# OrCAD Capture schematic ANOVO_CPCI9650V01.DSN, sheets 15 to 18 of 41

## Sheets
15 -ICH8-M HOST (1 of 4),3*SATA: size C; title: 15--ICH8-M HOST (1 of 4),3*SATA
16 -ICH8-M PCI E(2 of 4): size C; title: 16--ICH8-M PCI E(2 of 4)
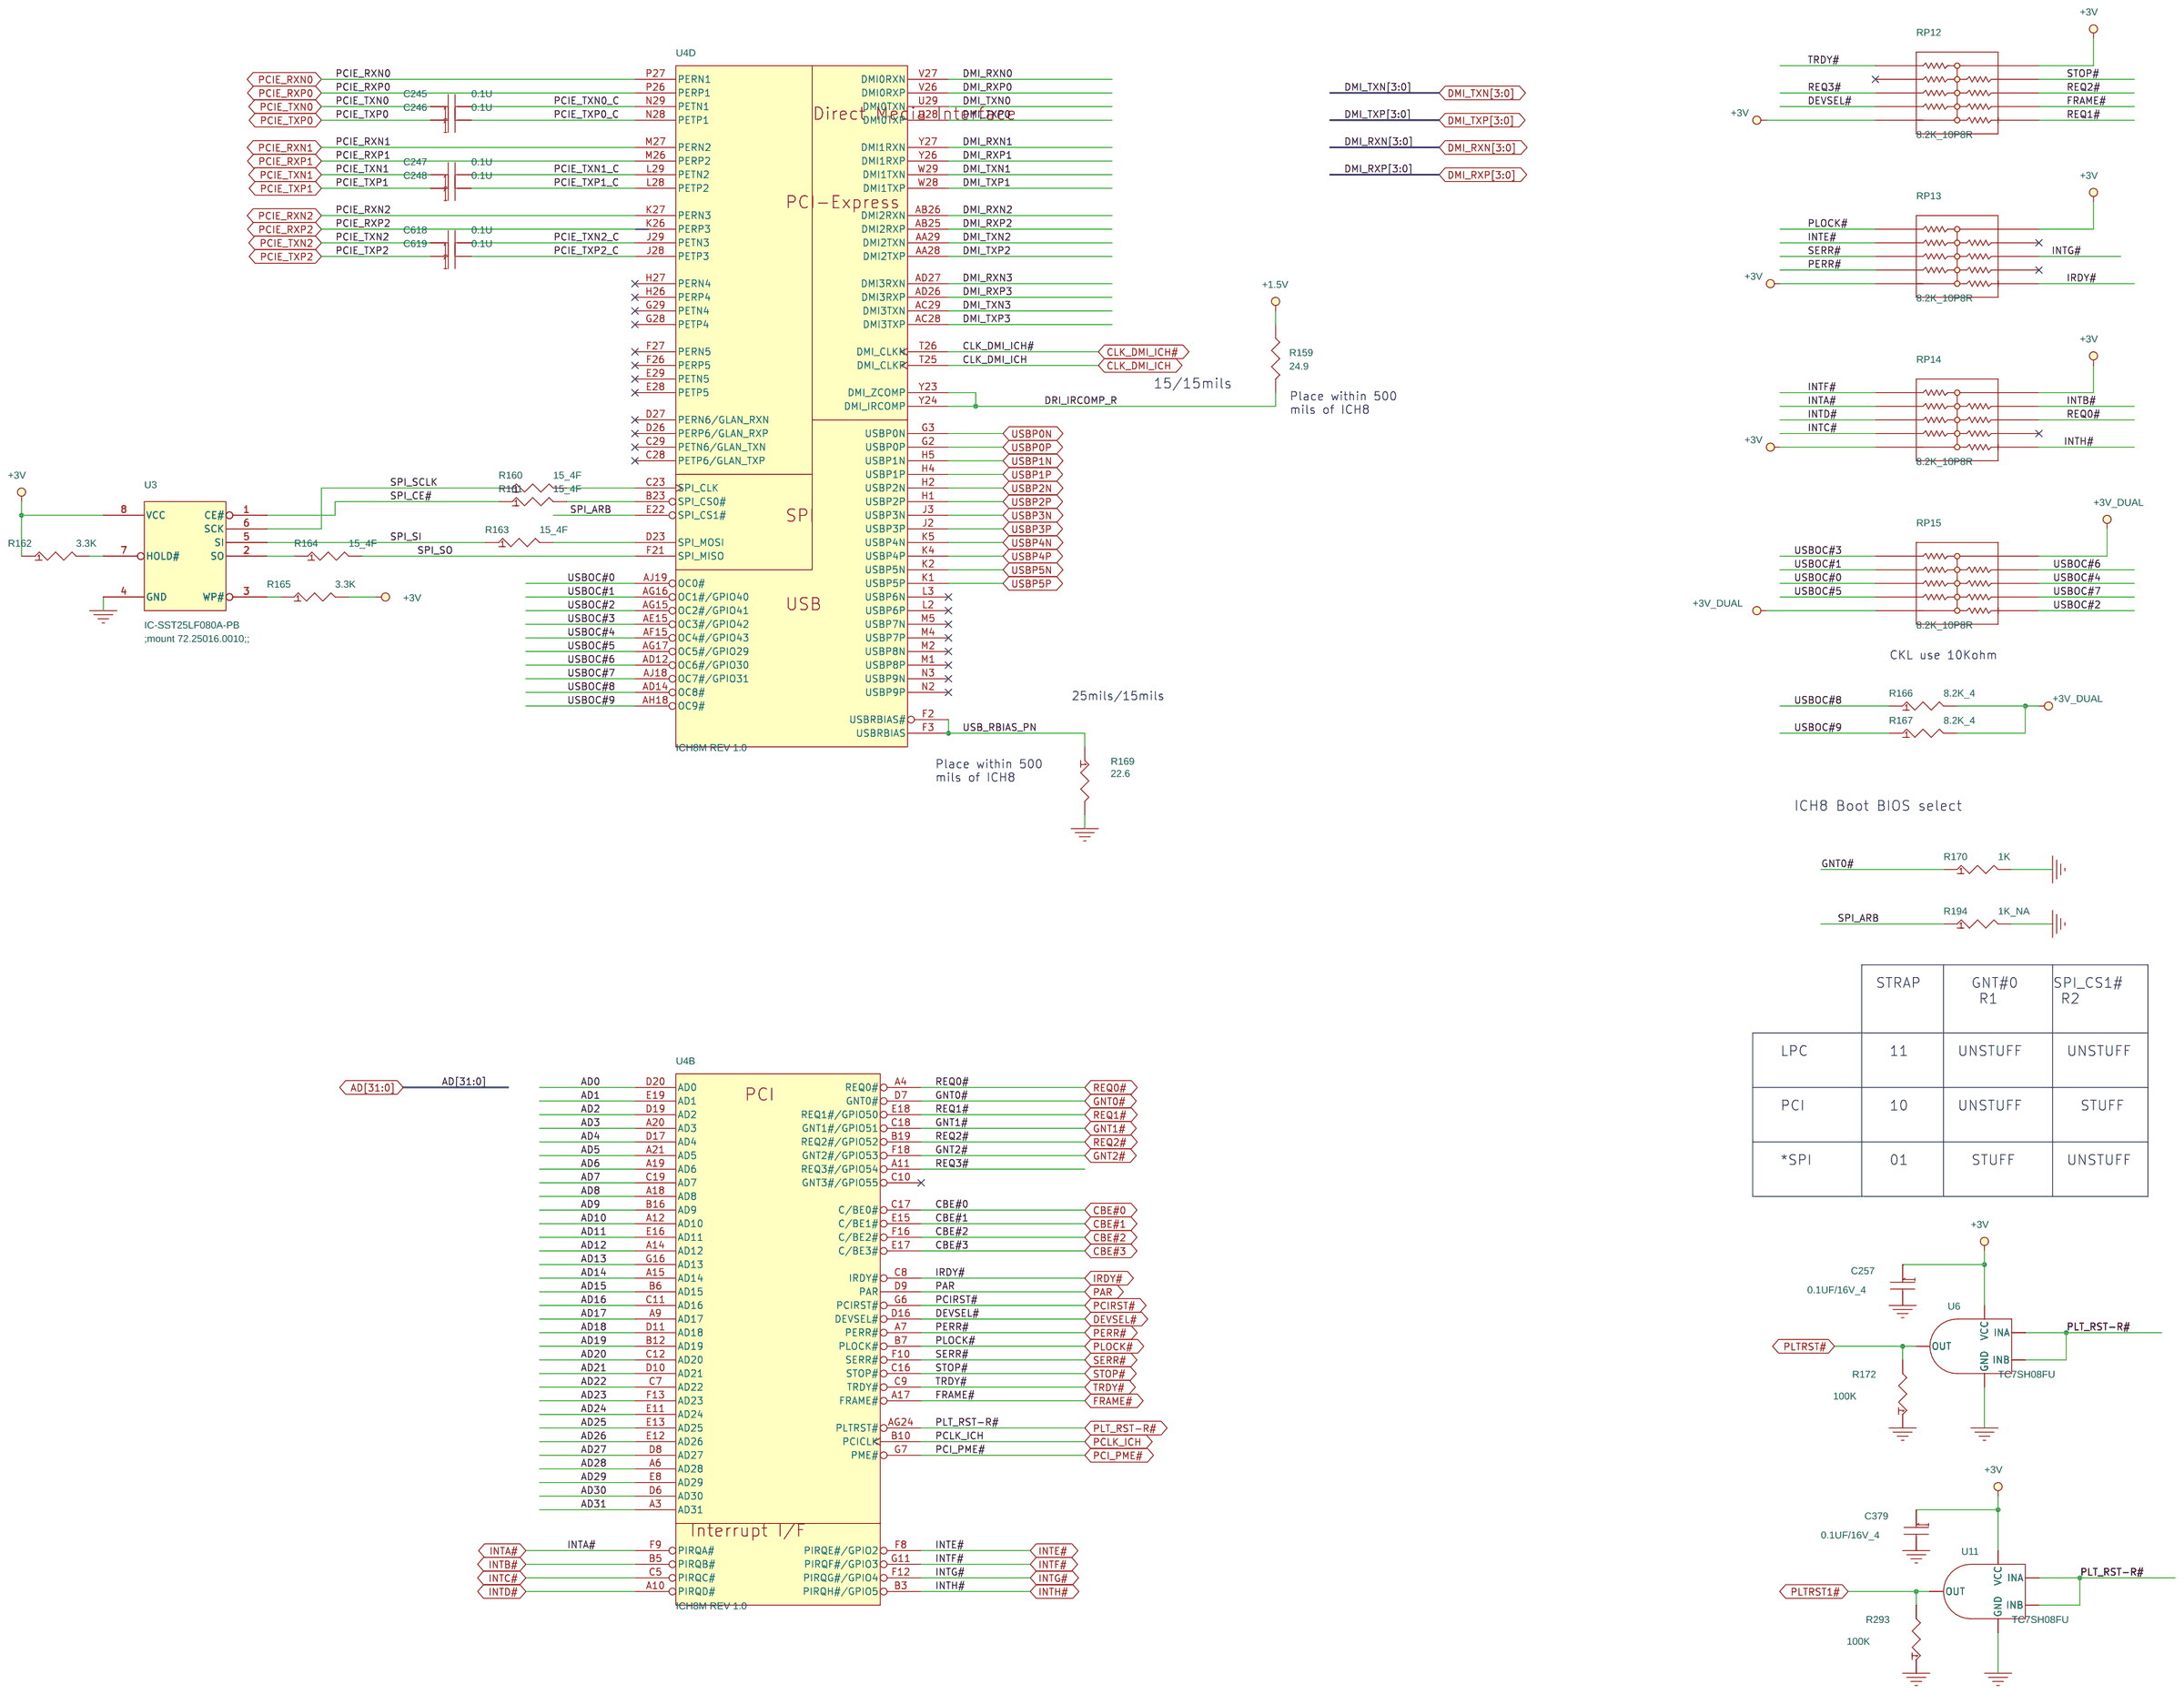
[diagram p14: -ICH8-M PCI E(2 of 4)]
17 -ICH8-M GPIO (3 of 4): size C; title: 17--ICH8-M GPIO (3 of 4)
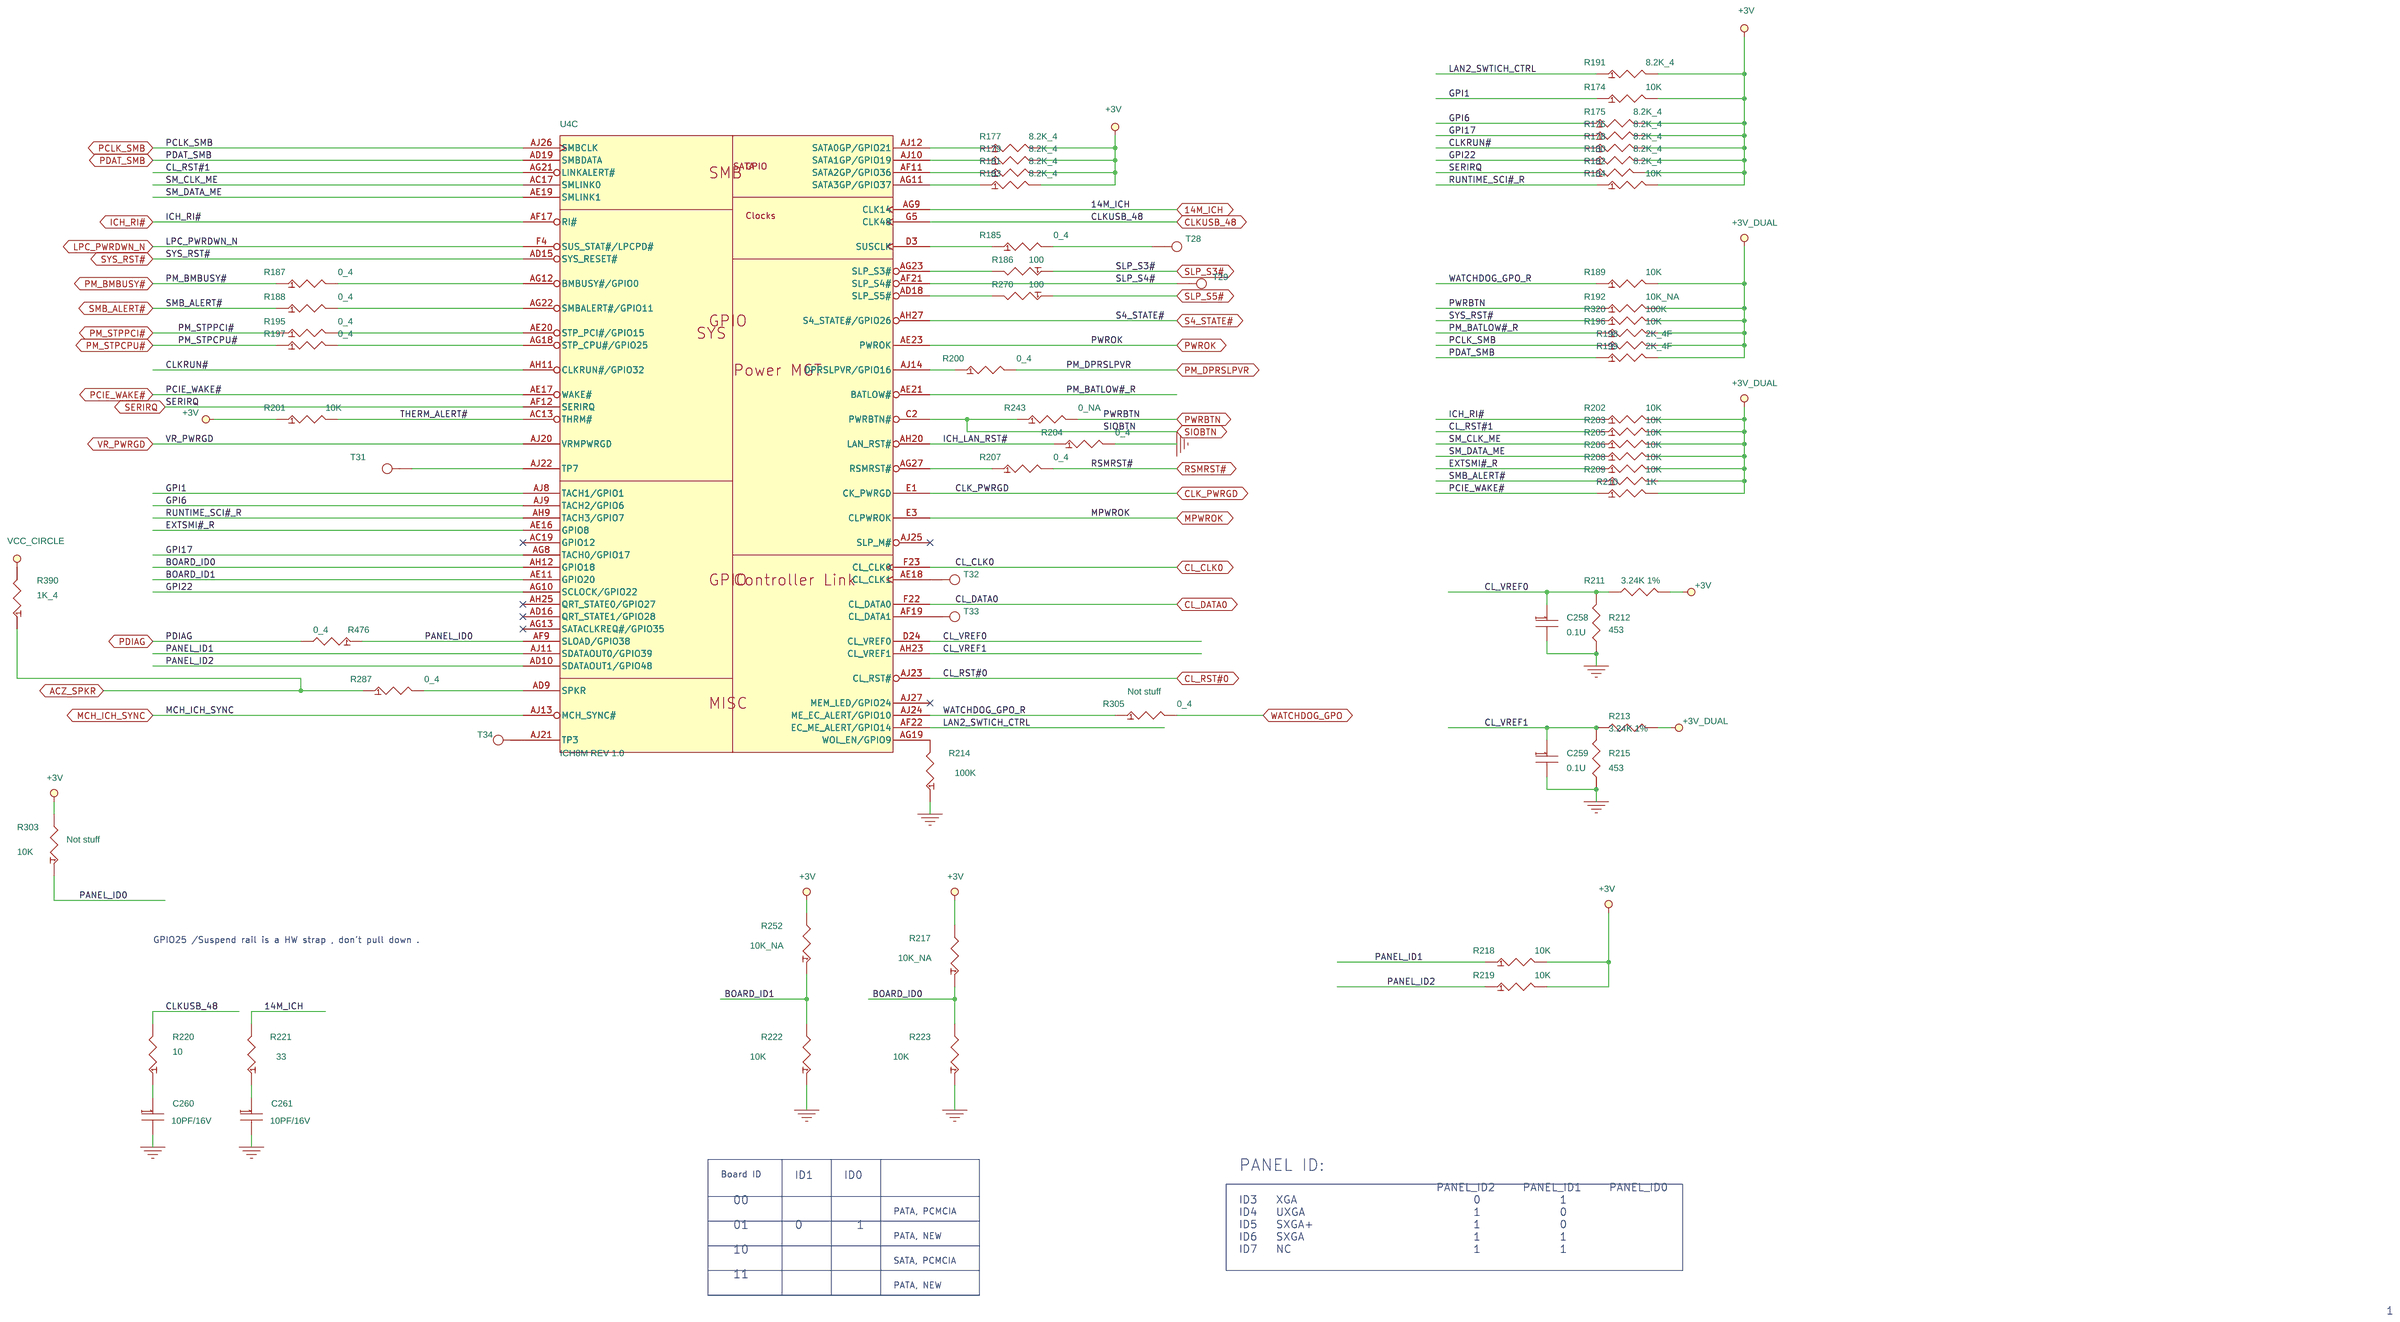
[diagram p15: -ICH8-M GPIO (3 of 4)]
18 -ICH8-M Power (4 of 4): size C; title: 18--ICH8-M Power (4 of 4)
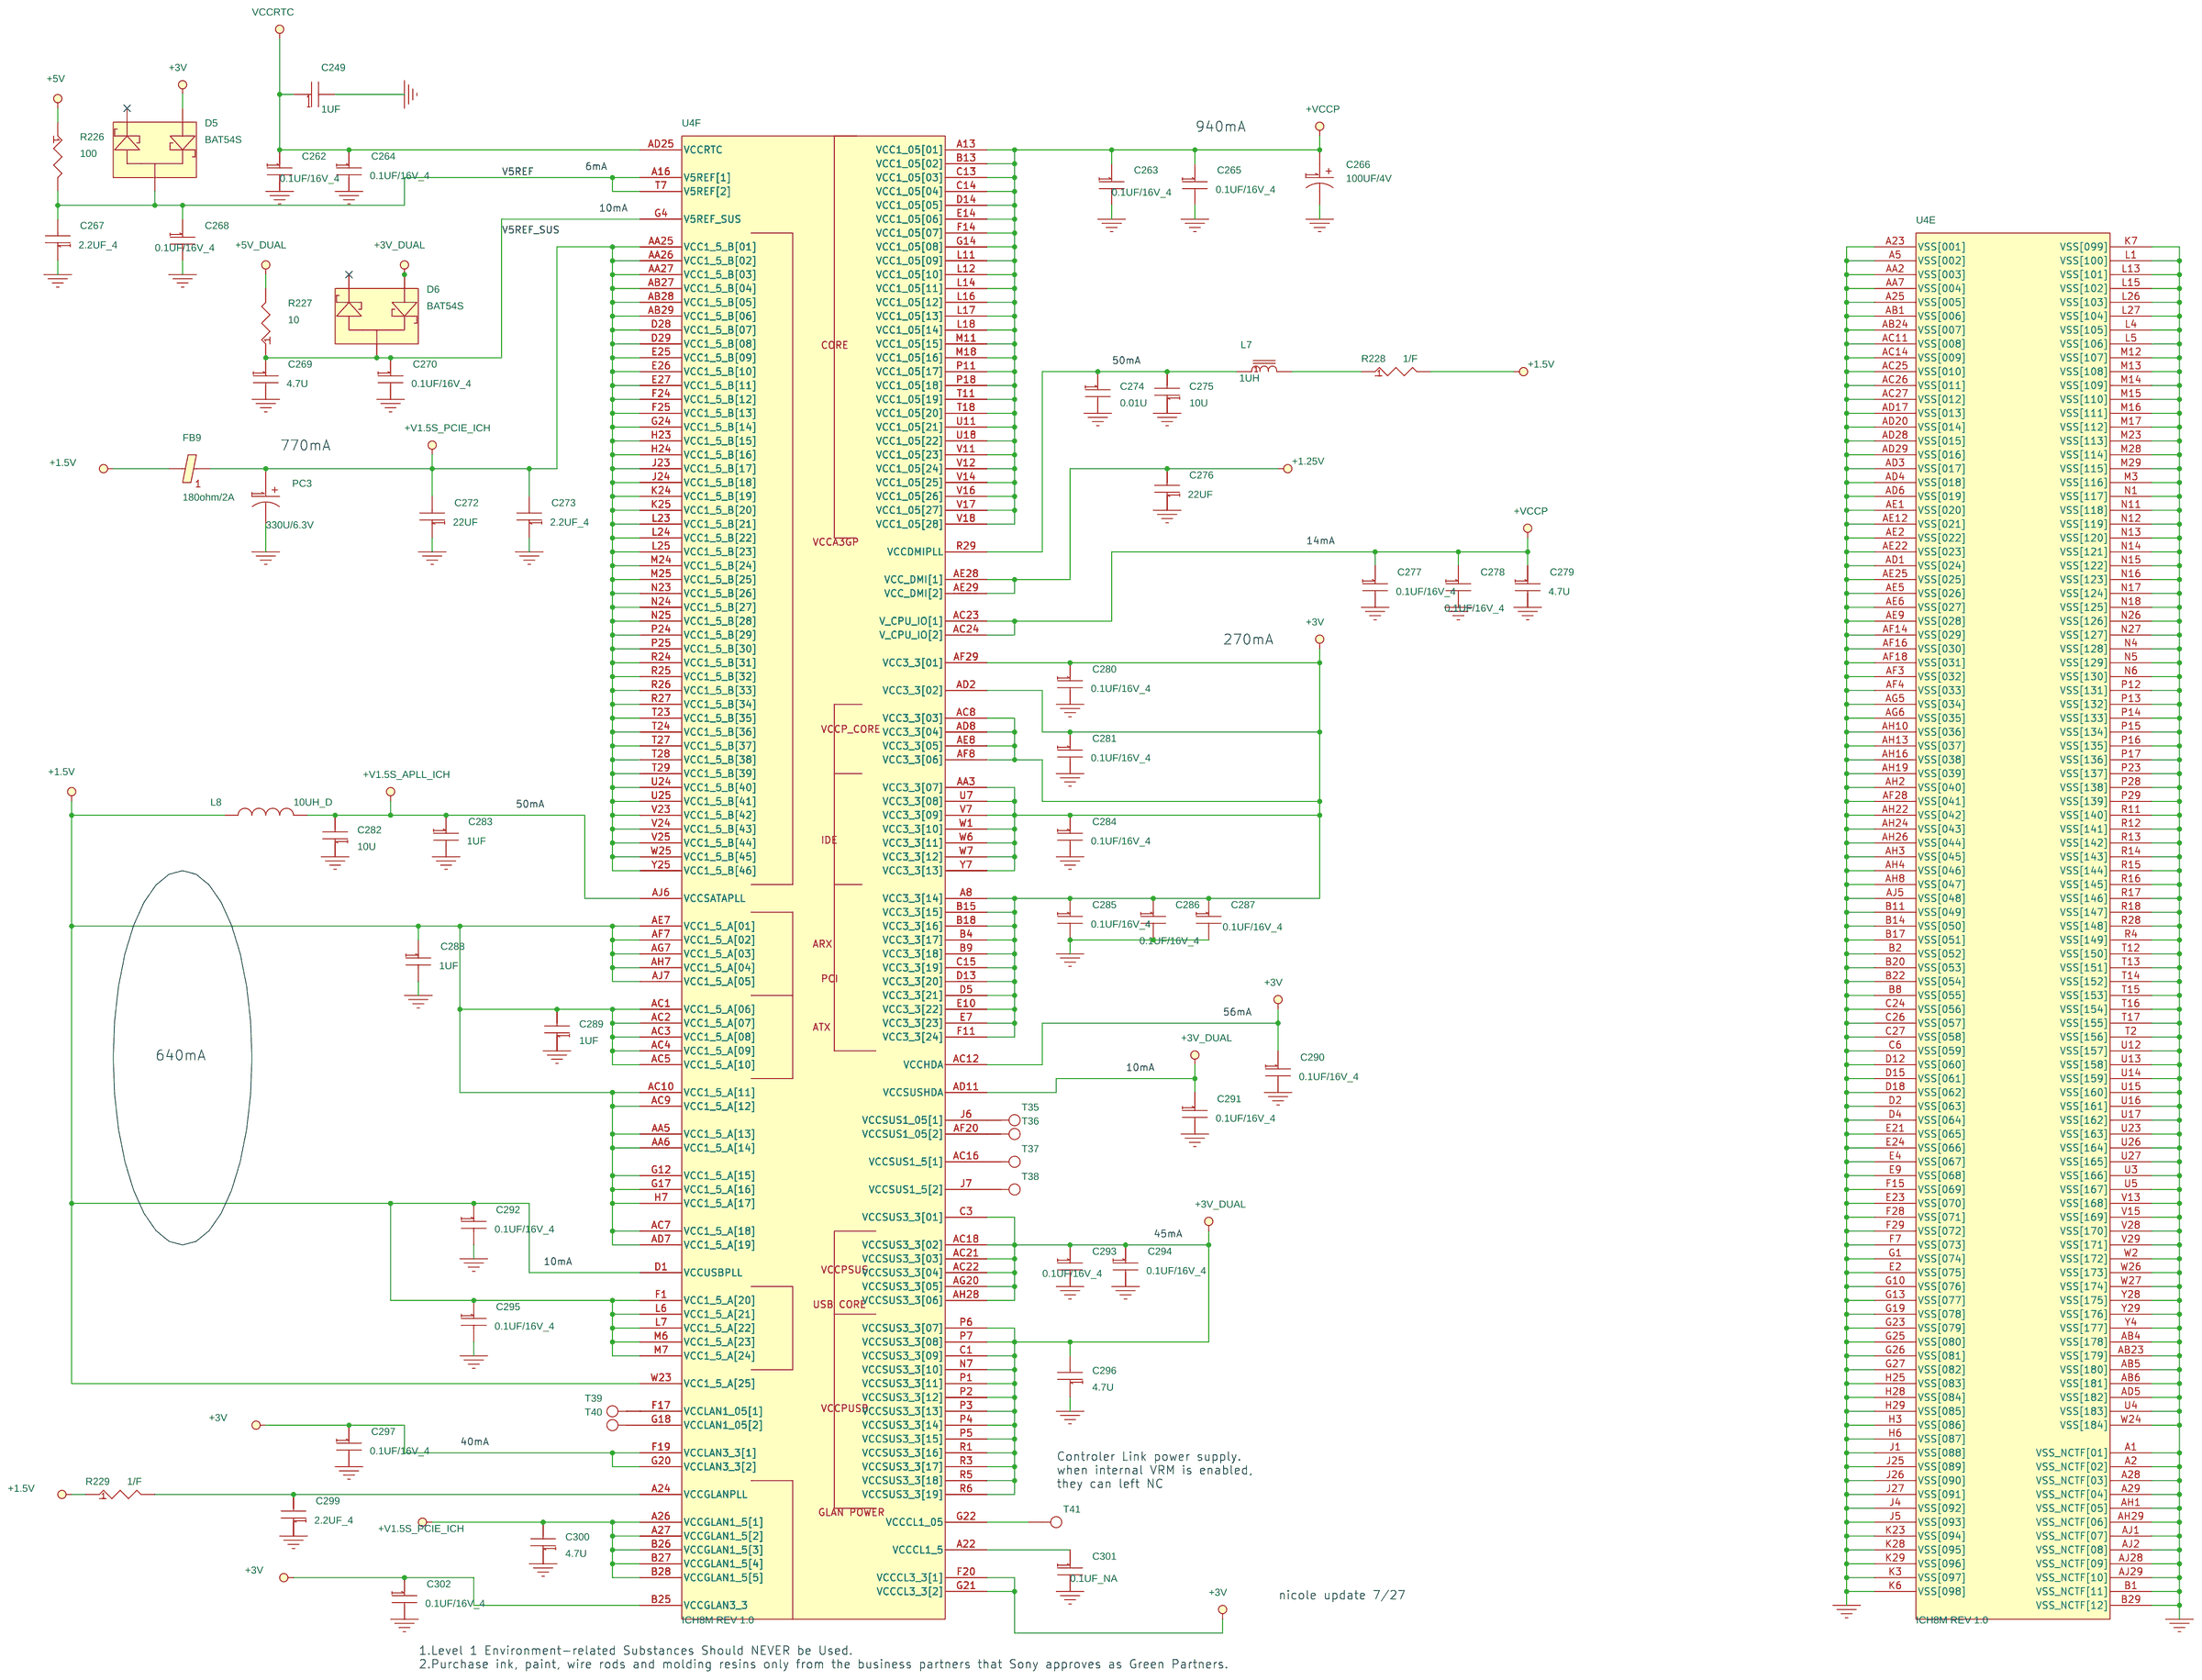
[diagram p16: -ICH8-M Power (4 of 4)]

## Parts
sheet -ICH8-M GPIO (3 of 4)
C258  0.1U  [0402D]
C259  0.1U  [0402D]
C260  10PF/16V  [0402D]
C261  10PF/16V  [0402D]
R174  10K  [0402D]
R175  8.2K_4  [0402D]
R176  8.2K_4  [0402D]
R177  8.2K_4  [0402D]
R178  8.2K_4  [0402D]
R179  8.2K_4  [0402D]
R180  8.2K_4  [0402D]
R181  8.2K_4  [0402D]
R182  8.2K_4  [0402D]
R183  8.2K_4  [0402D]
R184  10K  [0402D]
R185  0_4  [0402D]
R186  100  [0402D]
R187  0_4  [0402D]
R188  0_4  [0402D]
R189  10K  [0402D]
R191  8.2K_4  [0402D]
R192  10K_NA  [0402D]
R195  0_4  [0402D]
R196  10K  [0402D]
R197  0_4  [0402D]
R198  2K_4F  [0402D]
R199  2K_4F  [0402D]
R200  0_4  [0402D]
R201  10K  [0402D]
R202  10K  [0402D]
R203  10K  [0402D]
R204  0_4  [0402D]
R205  10K  [0402D]
R206  10K  [0402D]
R207  0_4  [0402D]
R208  10K  [0402D]
R209  10K  [0402D]
R210  1K  [0402D]
R211  3.24K 1%  [0603D]
R212  453  [0603D]
R213  3.24K 1%  [0603D]
R214  100K  [0402D]
R215  453  [0603D]
R217  10K_NA  [0402D]
R218  10K  [0402D]
R219  10K  [0402D]
R220  10  [0402D]
R221  33  [0402D]
R222  10K  [0402D]
R223  10K  [0402D]
R243  0_NA  [0402D]
R252  10K_NA  [0402D]
R270  100  [0402D]
R287  0_4  [0402D]
R303  10K  [0402D]
R305  0_4  [0402D]
R320  100K  [0402D]
R390  1K_4  [0402D]
R476  0_4  [0402D]
T28  PAD  [pad-c3050]
T29  PAD  [pad-c3050]
T31  PAD  [pad-c3050]
T32  PAD  [pad-c3050]
T33  PAD  [pad-c3050]
T34  PAD  [pad-c3050]
U4  ICH8M REV 1.0  [bga676-intel-ich8m]  (sections A,B,C,D,E,F)
sheet -ICH8-M HOST (1 of 4),3*SATA
BAT1  BATT  [bat_h3-a]
BATTERY1  Battery
C229  1UF  [0402D]
C230  18PF  [0603D]
C231  1UF  [0402D]
C232  18PF  [0603D]
C237  0.01U  [0402D]
C238  0.01U  [0402D]
C239  0.01U  [0402D]
C240  0.01U  [0402D]
C241  0.01U  [0402D]
C242  0.01U  [0402D]
C243  0.01U  [0402D]
C244  0.01U  [0402D]
C251  0.01U  [0402D]
C252  0.01U  [0402D]
C253  0.01U  [0402D]
C254  0.01U  [0402D]
D3  BAT54C  [SOT23N_5]
HEAD1  1x3 PIN  [conn_3b]
R130  20K  [0402D]
R131  1K  [0402D]
R132  1M_4  [0402D]
R133  10M_4  [0402D]
R134  10K  [0402D]
R135  10K  [0402D]
R136  56  [0402D]
R137  56_NA  [0402D]
R138  0_NA  [0402D]
R139  0_NA  [0402D]
R140  0_4  [0402D]
R141  24.9  [0402D]
R142  0_4  [0402D]
R143  56  [0402D]
R144  24.9  [0402D]
R145  10K  [0402D]
R146  24.9  [0402D]
R147  33  [0402D]
R148  330K  [0402D]
R149  330K  [0402D]
R152  33  [0402D]
R155  1K  [0402D]
R156  1K  [0402D]
R157  33  [0402D]
R158  33  [0402D]
T27  PAD  [pad-c3050]
Y2  32.768KHZ  [MC-306]
sheet -ICH8-M PCI E(2 of 4)
C245  0.1U  [0402D]
C246  0.1U  [0402D]
C247  0.1U  [0402D]
C248  0.1U  [0402D]
C257  0.1UF/16V_4  [0402D]
C379  0.1UF/16V_4  [0402D]
C618  0.1U  [0402D]
C619  0.1U  [0402D]
R159  24.9  [0402D]
R160  15_4F  [0402D]
R161  15_4F  [0402D]
R162  3.3K  [0402D]
R163  15_4F  [0402D]
R164  15_4F  [0402D]
R165  3.3K  [0402D]
R166  8.2K_4  [0402D]
R167  8.2K_4  [0402D]
R169  22.6  [0603D]
R170  1K  [0402D]
R172  100K  [0402D]
R194  1K_NA  [0402D]
R293  100K  [0402D]
RP12  8.2K_10P8R  [10P8R]
RP13  8.2K_10P8R  [10P8R]
RP14  8.2K_10P8R  [10P8R]
RP15  8.2K_10P8R  [10P8R]
U3  IC-SST25LF080A-PB  [I-SSTS2A-8P-S75X25-1D27MM]
U6  TC7SH08FU  [SSOP5_TOSHIBA]
U11  TC7SH08FU  [SSOP5_TOSHIBA]
sheet -ICH8-M Power (4 of 4)
C249  1UF  [0402D]
C262  0.1UF/16V_4  [0402D]
C263  0.1UF/16V_4  [0402D]
C264  0.1UF/16V_4  [0402D]
C265  0.1UF/16V_4  [0402D]
C266  100UF/4V  [C3530]
C267  2.2UF_4  [0402D]
C268  0.1UF/16V_4  [0402D]
C269  4.7U  [0805D]
C270  0.1UF/16V_4  [0402D]
C272  22UF  [0805D]
C273  2.2UF_4  [0402D]
C274  0.01U  [0402D]
C275  10U  [0805D]
C276  22UF  [0805D]
C277  0.1UF/16V_4  [0402D]
C278  0.1UF/16V_4  [0402D]
C279  4.7U  [0805D]
C280  0.1UF/16V_4  [0402D]
C281  0.1UF/16V_4  [0402D]
C282  10U  [0805D]
C283  1UF  [0402D]
C284  0.1UF/16V_4  [0402D]
C285  0.1UF/16V_4  [0402D]
C286  0.1UF/16V_4  [0402D]
C287  0.1UF/16V_4  [0402D]
C288  1UF  [0402D]
C289  1UF  [0402D]
C290  0.1UF/16V_4  [0402D]
C291  0.1UF/16V_4  [0402D]
C292  0.1UF/16V_4  [0402D]
C293  0.1UF/16V_4  [0402D]
C294  0.1UF/16V_4  [0402D]
C295  0.1UF/16V_4  [0402D]
C296  4.7U  [0805D]
C297  0.1UF/16V_4  [0402D]
C299  2.2UF_4  [0402D]
C300  4.7U  [0805D]
C301  0.1UF_NA  [0603D]
C302  0.1UF/16V_4  [0402D]
D5  BAT54S  [SOT23N_5]
D6  BAT54S  [SOT23N_5]
FB9  180ohm/2A  [0805D]
L7  1UH  [0805D]
L8  10UH_D  [0805D]
PC3  330U/6.3V  [1812A]
R226  100  [0402D]
R227  10  [0603D]
R228  1/F  [0402D]
R229  1/F  [0402D]
T35  PAD  [pad-c3050]
T36  PAD  [pad-c3050]
T37  PAD  [pad-c3050]
T38  PAD  [pad-c3050]
T39  PAD  [pad-c3050]
T40  PAD  [pad-c3050]
T41  PAD  [pad-c3050]

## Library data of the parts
C245-C248 C258 C259 C618 C619 = CAP_NP: ANOVO DESCRIPTION: CAP;0.1U ,16V ,10% ,0402 ,X7R ,SMT; ANOVO PART NUMBER: 272043104201; Part Type: CCAP
C260 C261 = CAP_NP: ANOVO DESCRIPTION: CAP;10P ,16V ,5% ,0402 ,NPO ,SMT; ANOVO PART NUMBER: 272043100101; BACKSIDE: 0; Part Type: CCAP; SMT: YES
R134 R135 R145 R174 R184 R189 R192 R196 R201-R203 R205 R206 R208 R209 R217-R219 R222 R223 R252 = R_v2: ANOVO DESCRIPTION: RES;10K ,1/16W ,5% ,0402 ,SMT; ANOVO PART NUMBER: 271040103301; BACKSIDE: 0; Part Type: RESISTOR; SMT: YES
R166 R167 R175-R183 R191 = R_v2: ANOVO DESCRIPTION: RES;8.2K ,1/16W ,5% ,0402 ,SMT; ANOVO PART NUMBER: 271040822301; BACKSIDE: 0; Part Type: RESISTOR; SMT: YES
R138-R140 R142 R185 R187 R188 R195 R197 R200 R204 R207 R243 R287 R476 = R_v2: ANOVO DESCRIPTION: RES;0 ,1/16W ,5% ,0402 ,SMT; ANOVO PART NUMBER: 271040000301; BACKCOMP: YES; BACKSIDE: YES; ID: 0; Part Type: RESISTOR; SMT: YES
R186 R226 R270 = R_v2: ANOVO DESCRIPTION: RES;100 ,1/16W ,1% ,0402 ,SMT; ANOVO PART NUMBER: 271040101101; Part Type: RESISTOR
R198 R199 = R_v2: ANOVO DESCRIPTION: RES;2K ,1/16W ,5% ,0402 ,SMT; ANOVO PART NUMBER: 271040202301; Part Type: RESISTOR
R131 R155 R156 R170 R210 = R_v2: ANOVO DESCRIPTION: RES;1K ,1/16W ,1% ,0402 ,SMT; ANOVO PART NUMBER: 271040102101; Part Type: RESISTOR
R211 R213 = R_0: ANOVO DESCRIPTION: RES,3.24K,1/10W,1%,0603,SMT; ANOVO PART NUMBER: 271071324111; Lead Free: EP; Part Number: CS23243F905; Part Type: CHIP; Res: 3.24K; Tolerance: 1%
R212 R215 = R_0: ANOVO DESCRIPTION: RES,453,1/10W,1%,0603,SMT; ANOVO PART NUMBER: 271071453011; Part Type: RESISTOR
R172 R214 R293 R320 = R_v2: ANOVO DESCRIPTION: RES;100K ,1/16W ,5% ,0402 ,SMT; ANOVO PART NUMBER: 271040104301; Part Type: RESISTOR
R220 = R_v2: ANOVO DESCRIPTION: RES;10 ,1/16W ,5% ,0402 ,SMT; ANOVO PART NUMBER: 271040100301; Part Type: RESISTOR; SMT: YES
R147 R152 R157 R158 R221 = R_v2: ANOVO DESCRIPTION: RES;33 ,1/16W ,5% ,0402 ,SMT; ANOVO PART NUMBER: 271040330301; BACKSIDE: 0; Part Type: RESISTOR; SMT: YES
R303 = R_v2: ANOVO DESCRIPTION: RES;10K ,1/16W ,5% ,0402 ,SMT; ANOVO PART NUMBER: 271040103301; BACKSIDE: 0; DUMMY: Not stuff; Part Type: RESISTOR; SMT: YES
R305 = R_v2: ANOVO DESCRIPTION: RES;0 ,1/16W ,5% ,0402 ,SMT; ANOVO PART NUMBER: 271040000301; BACKCOMP: YES; BACKSIDE: YES; DUMMY: Not stuff; ID: 0; Part Type: RESISTOR; SMT: YES
R390 = R_v2: ANOVO DESCRIPTION: RES;1K ,1/16W ,1% ,0402 ,SMT; ANOVO PART NUMBER: 271040102101; POWER: 1/16W; Part Type: RESISTOR
T27-T29 T35-T41 = PAD_1: 8ND PART FIELD: BOT; Function Code: CLG; Part Number: *
T31-T34 = PAD_1: Function Code: ICH; Part Number: *
U4 = IC,ICH8M,BGA676,12-01,rev1p0: ANOVO DESCRIPTION: IC,NH82801HBM,ICH8M,BGA,676B,Intel; ANOVO PART NUMBER: 284508280181; Function Code: CLG; Part Number: AJ0QM440T11
BAT1 = BATT_HOLDER: AMCO/562-2T1; Component_Name: BATT HOLDER; Critical_Part: N; Data_Sheet: K:\DataSheet\12-CONNECTOR\12-201110021.pdf; Database_Update: 2001/10/26; Manufacturer: ËÕ¬Ó; Package_Type: DIP; Part Number: 12-201110021; Part Type: 12CONNECTOR\OTHER; QVL_Approve: N; Sourcer: ³\¨Ø¬Â  (P7502); Status: «ØÄ³¥Î®Æ; Vendor: ¹Å¿A
BATTERY1 = BATT: BATTERY 3V/LITHIUM; Device: 121000000; Part Number: 121000000; ROOM: ICH4; SMT: NO
C229 C231 C249 C283 C288 C289 = CAP_NP: ANOVO DESCRIPTION: CAP, 1UF, 6.3V ,10%, 0402, X7R ,SMT; ANOVO PART NUMBER: 272041105200; Part Type: CCAP
C230 C232 = CAP_NP: ANOVO DESCRIPTION: CAP;18P ,50V ,5% ,0603 ,NPO ,SMT; ANOVO PART NUMBER: 272075180101; BACKSIDE: 0; Part Type: CCAP; SMT: YES
C237-C244 C251-C254 C274 = CAP_NP: ANOVO DESCRIPTION: CAP;0.01U ,16V ,10% ,0402 ,X7R ,SMT; ANOVO PART NUMBER: 272043103201; Part Type: CCAP
D3 = 288100054051: ANOVO DESCRIPTION: DIODE;BAT54C,SCHOTTKY DIODE,SOT23; ANOVO PART NUMBER: 288100054011
HEAD1 = HEADER_1x3: header 1x3 pin; ANOVO DESCRIPTION: CON;DIP;HDR;3P*1;2.54mm pitch;ST;Gold;Zhiwei; ANOVO PART NUMBER: 331010003000; BACKCOMP: NO; BACKSIDE: NO; Part Number: 131000001; SMT: NO
R130 = R_0: ANOVO DESCRIPTION: RES;20K ,1/16W ,1% ,0402 ,SMT; ANOVO PART NUMBER: 271040203101; Part Type: RESISTOR; SMT: YES
R132 = R_v2: ANOVO DESCRIPTION: RES;1M ,1/16W ,5% ,0402 ,SMT; ANOVO PART NUMBER: 271040105301; BACKSIDE: 0; Part Type: RESISTOR; SMT: YES
R133 = R_v2: ANOVO DESCRIPTION: RES;10M ,1/16W ,5% ,0402 ,SMT; ANOVO PART NUMBER: 271040106301; BACKSIDE: 0; Part Type: RESISTOR; SMT: YES
R136 R137 R143 = R_v2: ANOVO DESCRIPTION: RES,56 ,1/16W ,5%, 0402, SMT; ANOVO PART NUMBER: 271040560301; BACKSIDE: 0; Part Type: RESISTOR
R141 = R_0: ANOVO DESCRIPTION: RES;24.9 ,1/16W ,1% ,0402 ,SMT; ANOVO PART NUMBER: 271040249811; Function Code: CLG; POWER: 1/16W; Part Number: CS02492FB29; Part Type: RESISTOR; Size: 0402; Tolerance: 1%; Watt: 1/16W
R144 = R_20: 8ND PART FIELD: BOT; ANOVO DESCRIPTION: RES;24.9 ,1/16W ,1% ,0402 ,SMT; ANOVO PART NUMBER: 271040249811; Function Code: CLG; POWER: 1/16W; Part Description: RES CHIP 24.9 1/16W +-1%(0402) L-F; Part Number: CS02492FB29; Part Type: RESISTOR
R146 = R_15: 8ND PART FIELD: TOP; ANOVO DESCRIPTION: RES;24.9 ,1/16W ,1% ,0402 ,SMT; ANOVO PART NUMBER: 271040249811; Function Code: CLG; POWER: 1/16W; Part Description: RES CHIP 24.9 1/16W +-1%(0402) L-F; Part Number: CS02492FB29; Part Type: RESISTOR
R148 R149 = R_v2: ANOVO DESCRIPTION: RES;330K ,1/16W ,5% ,0402 ,SMT; ANOVO PART NUMBER: 271040334301; POWER: 1/16w; Part Type: RESISTOR
Y2 = CRYSTAL_0: 8ND PART FIELD: BOT; ANOVO DESCRIPTION: Xtal,32.768KHz,+-10ppm,12.5pF,3080,4P,SMT,JMT; ANOVO PART NUMBER: 274013272100; Function Code: CLG; Part Description: XTAL 32.768KHZ +-10PPM 9H03200299 L-F; Part Number: BG332768909
C257 C262-C265 C268 C270 C277 C278 C280 C281 C284-C287 C290-C295 C297 C302 C379 = CAP_NP: ANOVO DESCRIPTION: CAP;0.1U ,16V ,+80-20% ,0402 ,Y5V ,SMT; ANOVO PART NUMBER: 272043104401; BACKSIDE: 0; Part Type: CCAP; SMT: YES
R159 = R_8: 8ND PART FIELD: BOT; ANOVO DESCRIPTION: RES;24.9 ,1/16W ,1% ,0402 ,SMT; ANOVO PART NUMBER: 271040249811; Function Code: CLG; POWER: 1/16W; Part Description: RES CHIP 24.9 1/16W +-1%(0402) L-F; Part Number: CS02492FB29; Part Type: RESISTOR
R160 R161 R163 R164 = R_v2: ANOVO DESCRIPTION: RES;15 ,1/16W ,1% ,0402 ,SMT; ANOVO PART NUMBER: 271040150101; BACKSIDE: 0; Part Type: RESISTOR; SMT: YES
R162 R165 = R_v2: ANOVO DESCRIPTION: RES;3.3K ,1/16W ,5% ,0402 ,SMT; ANOVO PART NUMBER: 271040332301; BACKSIDE: 0; Part Type: RESISTOR; SMT: YES
R169 = R_v2: ANOVO DESCRIPTION: RES;22.6 ,1/10W ,1% ,0603 ,SMT; ANOVO PART NUMBER: 271071226811; BACKSIDE: 0; Part Type: RESISTOR; SMT: YES
R194 = R_v2: ANOVO DESCRIPTION: RES,1K   ,1/16W,5% ,0402,SMT; ANOVO PART NUMBER: 271071102401; BACKSIDE: 0; Part Type: RESISTOR; SMT: YES
RP12-RP15 = 10P8R-B: 8ND PART FIELD: TOP; ANOVO DESCRIPTION: RP;8.2K*8 ,10P ,1/32W ,5% ,0615,SMT; ANOVO PART NUMBER: 271565822301; BACKSIDE: 0; SMT: YES
U3 = IC-SST25LF080A-PB: IC FLASH SST25LF080A SOIC 8P; ANOVO DESCRIPTION: IC;EEPROM,SST25VF016B-50-4C-S2AF,S08,SST; ANOVO PART NUMBER: 283402501601; data sheet: ftp://datasheet:datasheet@aofs.aopen.com.tw/PASSIVE/IC-SST25LF080A-PB; note: ;mount 72.25016.0010;;; part number: 72.25080.A590
U6 U11 = TC7SH08FU
C266 = CAP_T: ANOVO DESCRIPTION: TANCAP;100U ,4V,+-20%,C3530,SMT; ANOVO PART NUMBER: 272631070011; Part Type: TAN CAP
C267 C273 C299 = CAP_NP: ANOVO DESCRIPTION: CAP;2.2U ,6.3V ,10% ,0402 ,X7R ,SMT; ANOVO PART NUMBER: 272041225201
C269 C279 C296 C300 = CAP_NP: ANOVO DESCRIPTION: CAP;4.7U ,10V ,+80-20% ,0805 ,Y5V ,SMT; ANOVO PART NUMBER: 272002475401; Part Type: CCAP
C272 C276 = CAP_NP: ANOVO DESCRIPTION: CAP,22U ,CR,16V ,+80-20%,0805,Y5V,SMT,TAIYO; ANOVO PART NUMBER: 272003226401; BACKSIDE: 0; Part Type: CCAP; SMT: YES
C275 C282 = CAP_NP: ANOVO DESCRIPTION: CAP;10U,10V,+80-20%,0805,Y5V,SMT; ANOVO PART NUMBER: 272002106401; Part Type: CCAP
C301 = CAP_NP: ANOVO DESCRIPTION: CAP;0.1U ,16V ,10% ,0402 ,X7R ,SMT; ANOVO PART NUMBER: 272043104201; BACKSIDE: 0; Part Type: CCAP; SMT: YES
D5 D6 = BAT54S: ANOVO DESCRIPTION: DIODE;BAT54S,SCHOTTKY DIODE,SOT23; ANOVO PART NUMBER: 288100054021; BACKSIDE: 0; Part Type: SCHOTTKY; SMT: YES; Datasheet: \\Rdserver\norcocis\datasheet\DIODE\fairchild\BAT54.pdf
FB9 = FERRITE_BEAD: ANOVO DESCRIPTION: FERRITE CHIP;180 OHM/100MHZ,2A,0805,SMT; ANOVO PART NUMBER: 273001814300; BACKSIDE: 0; Part Type: FERRITE BEAD; SMT: YES
L7 = INDUCTOR: ANOVO DESCRIPTION: INDUCTOR;SMT;1UH;+-10%;50MA;0805;CHILSIN; ANOVO PART NUMBER: 275001050300; BACKSIDE: 0; SMT: YES
L8 = INDUCTOR_7: 2ND PART FIELD: CV01001KZ45; ANOVO DESCRIPTION: INDUCTOR;10UH,10%,100mA,0805,SMT; ANOVO PART NUMBER: 275001061300; BACKSIDE: 0; Function Code: CLG; NOTE: 3610pcs; Part Number: CV01001KZ45; Part Type: INDUCTOR; SMT: YES
PC3 = CAP_T: ANOVO DESCRIPTION: TANCAP,330U,6.3V,20%,D size, SMT; ANOVO PART NUMBER: 272633371011
R227 = R_v2: ANOVO DESCRIPTION: RES;10 ,1/10W ,1% ,0603 ,SMT; ANOVO PART NUMBER: 271071100101; BACKSIDE: 0; Part Type: RESISTOR; SMT: YES
R228 R229 = R_v2: ANOVO DESCRIPTION: RES;1,1/16W,1%,0402,SMT; ANOVO PART NUMBER: 271040010101

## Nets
+1.5V: C288.1 C289.2 C292.1 C295.1 FB9.2 L8.1 R159.1 R228.2 R229.1 U4.AA5(VCC1_5_A[13]) U4.AA6(VCC1_5_A[14]) U4.AC1(VCC1_5_A[06]) U4.AC2(VCC1_5_A[07]) U4.AC3(VCC1_5_A[08]) U4.AC4(VCC1_5_A[09]) U4.AC5(VCC1_5_A[10]) U4.AC7(VCC1_5_A[18]) U4.AC9(VCC1_5_A[12]) U4.AC10(VCC1_5_A[11]) U4.AD7(VCC1_5_A[19]) U4.AE7(VCC1_5_A[01]) U4.AF7(VCC1_5_A[02]) U4.AG7(VCC1_5_A[03]) U4.AH7(VCC1_5_A[04]) U4.AJ7(VCC1_5_A[05]) U4.D1(VCCUSBPLL) U4.F1(VCC1_5_A[20]) U4.G12(VCC1_5_A[15]) U4.G17(VCC1_5_A[16]) U4.H7(VCC1_5_A[17]) U4.L6(VCC1_5_A[21]) U4.L7(VCC1_5_A[22]) U4.M6(VCC1_5_A[23]) U4.M7(VCC1_5_A[24]) U4.W23(VCC1_5_A[25]) ; also on sheet 6 12 32 33
+1.25V: C276.2 U4.AE28(VCC_DMI[1]) U4.AE29(VCC_DMI[2]) ; also on sheet 9 12 21 32
+3V: C257.1 C280.1 C281.1 C284.1 C285.1 C286.1 C287.1 C290.1 C297.1 C302.1 C379.1 D5.1 R134.2 R135.2 R145.2 R162.1 R165.2 R174.2 R175.2 R176.2 R177.2 R178.2 R179.2 R180.2 R181.2 R182.2 R183.2 R184.2 R191.2 R201.1 R211.2 R217.2 R218.2 R219.2 R252.2 R303.2 R390.2 RP12.5 RP12.10 RP13.5 RP13.10 RP14.5 RP14.10 U3.8(VCC) U4.A8(VCC3_3[14]) U4.AA3(VCC3_3[07]) U4.AC8(VCC3_3[03]) U4.AC12(VCCHDA) U4.AD2(VCC3_3[02]) U4.AD8(VCC3_3[04]) U4.AE8(VCC3_3[05]) U4.AF8(VCC3_3[06]) U4.AF29(VCC3_3[01]) U4.B4(VCC3_3[17]) U4.B9(VCC3_3[18]) U4.B15(VCC3_3[15]) U4.B18(VCC3_3[16]) U4.B25(VCCGLAN3_3) U4.C15(VCC3_3[19]) U4.D5(VCC3_3[21]) U4.D13(VCC3_3[20]) U4.E7(VCC3_3[23]) U4.E10(VCC3_3[22]) U4.F11(VCC3_3[24]) U4.F19(VCCLAN3_3[1]) U4.F20(VCCCL3_3[1]) U4.G20(VCCLAN3_3[2]) U4.G21(VCCCL3_3[2]) U4.U7(VCC3_3[08]) U4.V7(VCC3_3[09]) U4.W1(VCC3_3[10]) U4.W6(VCC3_3[11]) U4.W7(VCC3_3[12]) U4.Y7(VCC3_3[13]) U6.5(VCC) U11.5(VCC) ; also on sheet 4 9 10 12 19 20 21 22 23 24 25 26 27 28 31 32 34 35 41
+3V_DUAL: C291.1 C293.1 C294.1 C296.2 D3.1 D6.1 R166.2 R167.2 R189.2 R192.2 R196.2 R198.2 R199.2 R202.2 R203.2 R205.2 R206.2 R208.2 R209.2 R210.2 R213.2 R320.2 RP15.5 RP15.10 U4.AC18(VCCSUS3_3[02]) U4.AC21(VCCSUS3_3[03]) U4.AC22(VCCSUS3_3[04]) U4.AD11(VCCSUSHDA) U4.AG20(VCCSUS3_3[05]) U4.AH28(VCCSUS3_3[06]) U4.C1(VCCSUS3_3[09]) U4.C3(VCCSUS3_3[01]) U4.N7(VCCSUS3_3[10]) U4.P1(VCCSUS3_3[11]) U4.P2(VCCSUS3_3[12]) U4.P3(VCCSUS3_3[13]) U4.P4(VCCSUS3_3[14]) U4.P5(VCCSUS3_3[15]) U4.P6(VCCSUS3_3[07]) U4.P7(VCCSUS3_3[08]) U4.R1(VCCSUS3_3[16]) U4.R3(VCCSUS3_3[17]) U4.R5(VCCSUS3_3[18]) U4.R6(VCCSUS3_3[19]) ; also on sheet 14 19 20 21 26 31 33 34 38 40 41
+5V: R226.1 ; also on sheet 21 22 23 24 25 26 27 29 30 31 32 33 34 35 40
+5V_DUAL: R227.2 ; also on sheet 21 25 27 30 31 33 34
+V1.5S_APLL_ICH: C282.2 C283.1 L8.2 U4.AJ6(VCCSATAPLL)
+V1.5S_PCIE_ICH: C272.2 C273.2 C300.2 FB9.1 PC3.1 R141.1 U4.A26(VCCGLAN1_5[1]) U4.A27(VCCGLAN1_5[2]) U4.AA25(VCC1_5_B[01]) U4.AA26(VCC1_5_B[02]) U4.AA27(VCC1_5_B[03]) U4.AB27(VCC1_5_B[04]) U4.AB28(VCC1_5_B[05]) U4.AB29(VCC1_5_B[06]) U4.B26(VCCGLAN1_5[3]) U4.B27(VCCGLAN1_5[4]) U4.B28(VCCGLAN1_5[5]) U4.D28(VCC1_5_B[07]) U4.D29(VCC1_5_B[08]) U4.E25(VCC1_5_B[09]) U4.E26(VCC1_5_B[10]) U4.E27(VCC1_5_B[11]) U4.F24(VCC1_5_B[12]) U4.F25(VCC1_5_B[13]) U4.G24(VCC1_5_B[14]) U4.H23(VCC1_5_B[15]) U4.H24(VCC1_5_B[16]) U4.J23(VCC1_5_B[17]) U4.J24(VCC1_5_B[18]) U4.K24(VCC1_5_B[19]) U4.K25(VCC1_5_B[20]) U4.L23(VCC1_5_B[21]) U4.L24(VCC1_5_B[22]) U4.L25(VCC1_5_B[23]) U4.M24(VCC1_5_B[24]) U4.M25(VCC1_5_B[25]) U4.N23(VCC1_5_B[26]) U4.N24(VCC1_5_B[27]) U4.N25(VCC1_5_B[28]) U4.P24(VCC1_5_B[29]) U4.P25(VCC1_5_B[30]) U4.R24(VCC1_5_B[31]) U4.R25(VCC1_5_B[32]) U4.R26(VCC1_5_B[33]) U4.R27(VCC1_5_B[34]) U4.T23(VCC1_5_B[35]) U4.T24(VCC1_5_B[36]) U4.T27(VCC1_5_B[37]) U4.T28(VCC1_5_B[38]) U4.T29(VCC1_5_B[39]) U4.U24(VCC1_5_B[40]) U4.U25(VCC1_5_B[41]) U4.V23(VCC1_5_B[42]) U4.V24(VCC1_5_B[43]) U4.V25(VCC1_5_B[44]) U4.W25(VCC1_5_B[45]) U4.Y25(VCC1_5_B[46])
+VCCP: C263.1 C265.1 C266.1 C277.1 C278.1 C279.1 R136.2 R137.2 R143.2 U4.A13(VCC1_05[01]) U4.AC23(V_CPU_IO[1]) U4.AC24(V_CPU_IO[2]) U4.B13(VCC1_05[02]) U4.C13(VCC1_05[03]) U4.C14(VCC1_05[04]) U4.D14(VCC1_05[05]) U4.E14(VCC1_05[06]) U4.F14(VCC1_05[07]) U4.G14(VCC1_05[08]) U4.L11(VCC1_05[09]) U4.L12(VCC1_05[10]) U4.L14(VCC1_05[11]) U4.L16(VCC1_05[12]) U4.L17(VCC1_05[13]) U4.L18(VCC1_05[14]) U4.M11(VCC1_05[15]) U4.M18(VCC1_05[16]) U4.P11(VCC1_05[17]) U4.P18(VCC1_05[18]) U4.T11(VCC1_05[19]) U4.T18(VCC1_05[20]) U4.U11(VCC1_05[21]) U4.U18(VCC1_05[22]) U4.V11(VCC1_05[23]) U4.V12(VCC1_05[24]) U4.V14(VCC1_05[25]) U4.V16(VCC1_05[26]) U4.V17(VCC1_05[27]) U4.V18(VCC1_05[28]) ; also on sheet 5 6 7 10 11 12 21 31 32
GND: BAT1.2(-) C229.2 C230.1 C231.1 C232.1 C249.2 C257.2 C258.2 C259.2 C260.2 C261.2 C262.2 C263.2 C264.2 C265.2 C266.2 C267.1 C268.2 C269.2 C270.2 C272.1 C273.1 C274.2 C275.1 C276.1 C277.2 C278.2 C279.2 C280.2 C281.2 C282.1 C283.2 C284.2 C285.2 C286.2 C287.2 C288.2 C289.1 C290.2 C291.2 C292.2 C293.2 C294.2 C295.2 C296.1 C297.2 C299.1 C300.1 C301.2 C302.2 C379.2 HEAD1.1 PC3.2 R146.1 R155.2 R156.2 R169.2 R170.2 R172.1 R194.2 R204.2 R212.1 R214.1 R215.1 R222.1 R223.1 R293.1 U3.4(GND) U4.A1(VSS_NCTF[01]) U4.A2(VSS_NCTF[02]) U4.A5(VSS[002]) U4.A23(VSS[001]) U4.A25(VSS[005]) U4.A28(VSS_NCTF[03]) U4.A29(VSS_NCTF[04]) U4.AA2(VSS[003]) U4.AA7(VSS[004]) U4.AB1(VSS[006]) U4.AB4(VSS[178]) U4.AB5(VSS[180]) U4.AB6(VSS[181]) U4.AB23(VSS[179]) U4.AB24(VSS[007]) U4.AC11(VSS[008]) U4.AC14(VSS[009]) U4.AC25(VSS[010]) U4.AC26(VSS[011]) U4.AC27(VSS[012]) U4.AD1(VSS[024]) U4.AD3(VSS[017]) U4.AD4(VSS[018]) U4.AD5(VSS[182]) U4.AD6(VSS[019]) U4.AD17(VSS[013]) U4.AD20(VSS[014]) U4.AD28(VSS[015]) U4.AD29(VSS[016]) U4.AE1(VSS[020]) U4.AE2(VSS[022]) U4.AE5(VSS[026]) U4.AE6(VSS[027]) U4.AE9(VSS[028]) U4.AE12(VSS[021]) U4.AE22(VSS[023]) U4.AE25(VSS[025]) U4.AF3(VSS[032]) U4.AF4(VSS[033]) U4.AF14(VSS[029]) U4.AF16(VSS[030]) U4.AF18(VSS[031]) U4.AF28(VSS[041]) U4.AG5(VSS[034]) U4.AG6(VSS[035]) U4.AH1(VSS_NCTF[05]) U4.AH2(VSS[040]) U4.AH3(VSS[045]) U4.AH4(VSS[046]) U4.AH8(VSS[047]) U4.AH10(VSS[036]) U4.AH13(VSS[037]) U4.AH16(VSS[038]) U4.AH19(VSS[039]) U4.AH22(VSS[042]) U4.AH24(VSS[043]) U4.AH26(VSS[044]) U4.AH29(VSS_NCTF[06]) U4.AJ1(VSS_NCTF[07]) U4.AJ2(VSS_NCTF[08]) U4.AJ5(VSS[048]) U4.AJ28(VSS_NCTF[09]) U4.AJ29(VSS_NCTF[10]) U4.B1(VSS_NCTF[11]) U4.B2(VSS[052]) U4.B8(VSS[055]) U4.B11(VSS[049]) U4.B14(VSS[050]) U4.B17(VSS[051]) U4.B20(VSS[053]) U4.B22(VSS[054]) U4.B29(VSS_NCTF[12]) U4.C6(VSS[059]) U4.C24(VSS[056]) U4.C26(VSS[057]) U4.C27(VSS[058]) U4.D2(VSS[063]) U4.D4(VSS[064]) U4.D12(VSS[060]) U4.D15(VSS[061]) U4.D18(VSS[062]) U4.E2(VSS[075]) U4.E4(VSS[067]) U4.E9(VSS[068]) U4.E21(VSS[065]) U4.E23(VSS[070]) U4.E24(VSS[066]) U4.F7(VSS[073]) U4.F15(VSS[069]) U4.F28(VSS[071]) U4.F29(VSS[072]) U4.G1(VSS[074]) U4.G10(VSS[076]) U4.G13(VSS[077]) U4.G19(VSS[078]) U4.G23(VSS[079]) U4.G25(VSS[080]) U4.G26(VSS[081]) U4.G27(VSS[082]) U4.H3(VSS[086]) U4.H6(VSS[087]) U4.H25(VSS[083]) U4.H28(VSS[084]) U4.H29(VSS[085]) U4.J1(VSS[088]) U4.J4(VSS[092]) U4.J5(VSS[093]) U4.J25(VSS[089]) U4.J26(VSS[090]) U4.J27(VSS[091]) U4.K3(VSS[097]) U4.K6(VSS[098]) U4.K7(VSS[099]) U4.K23(VSS[094]) U4.K28(VSS[095]) U4.K29(VSS[096]) U4.L1(VSS[100]) U4.L4(VSS[105]) U4.L5(VSS[106]) U4.L13(VSS[101]) U4.L15(VSS[102]) U4.L26(VSS[103]) U4.L27(VSS[104]) U4.M3(VSS[116]) U4.M12(VSS[107]) U4.M13(VSS[108]) U4.M14(VSS[109]) U4.M15(VSS[110]) U4.M16(VSS[111]) U4.M17(VSS[112]) U4.M23(VSS[113]) U4.M28(VSS[114]) U4.M29(VSS[115]) U4.N1(VSS[117]) U4.N4(VSS[128]) U4.N5(VSS[129]) U4.N6(VSS[130]) U4.N11(VSS[118]) U4.N12(VSS[119]) U4.N13(VSS[120]) U4.N14(VSS[121]) U4.N15(VSS[122]) U4.N16(VSS[123]) U4.N17(VSS[124]) U4.N18(VSS[125]) U4.N26(VSS[126]) U4.N27(VSS[127]) U4.P12(VSS[131]) U4.P13(VSS[132]) U4.P14(VSS[133]) U4.P15(VSS[134]) U4.P16(VSS[135]) U4.P17(VSS[136]) U4.P23(VSS[137]) U4.P28(VSS[138]) U4.P29(VSS[139]) U4.R4(VSS[149]) U4.R11(VSS[140]) U4.R12(VSS[141]) U4.R13(VSS[142]) U4.R14(VSS[143]) U4.R15(VSS[144]) U4.R16(VSS[145]) U4.R17(VSS[146]) U4.R18(VSS[147]) U4.R28(VSS[148]) U4.T2(VSS[156]) U4.T12(VSS[150]) U4.T13(VSS[151]) U4.T14(VSS[152]) U4.T15(VSS[153]) U4.T16(VSS[154]) U4.T17(VSS[155]) U4.U3(VSS[166]) U4.U4(VSS[183]) U4.U5(VSS[167]) U4.U12(VSS[157]) U4.U13(VSS[158]) U4.U14(VSS[159]) U4.U15(VSS[160]) U4.U16(VSS[161]) U4.U17(VSS[162]) U4.U23(VSS[163]) U4.U26(VSS[164]) U4.U27(VSS[165]) U4.V13(VSS[168]) U4.V15(VSS[169]) U4.V28(VSS[170]) U4.V29(VSS[171]) U4.W2(VSS[172]) U4.W24(VSS[184]) U4.W26(VSS[173]) U4.W27(VSS[174]) U4.Y4(VSS[177]) U4.Y28(VSS[175]) U4.Y29(VSS[176]) U6.3(GND) U11.3(GND) ; also on sheet 4 5 6 7 9 10 11 12 13 14 19 20 21 22 23 24 25 26 27 28 29 30 31 32 33 34 35 36 37 38 39 40 41
V5REF: C267.2 C268.1 D5.3 R226.2 U4.A16(V5REF[1]) U4.T7(V5REF[2])
V5REF_SUS: C269.1 C270.1 D6.3 R227.1 U4.G4(V5REF_SUS)
VCCRTC: C229.1 C249.1 C262.1 C264.1 D3.3 R130.2 R132.2 R148.1 R149.1 U4.AD25(VCCRTC) ; also on sheet 21
VCCRTC_3: D3.2 R131.2
14M_ICH: R221.2 U4.AG9(CLK14) ; also on sheet 4
ACZ_BCLK: R158.1 U4.AJ16(HDA_BIT_CLK)
ACZ_RST#: R152.1 U4.AE14(HDA_RST#)
ACZ_RST#_AUDIO: R152.2 ; also on sheet 23
ACZ_SDIN0: U4.AJ17(HDA_SDIN0) ; also on sheet 23
ACZ_SDOUT: R156.1 R157.1 U4.AE13(HDA_SDOUT)
ACZ_SDOUT_AUDIO: R157.2 ; also on sheet 23
ACZ_SPKR: R287.1 R390.1 ; also on sheet 23 25
ACZ_SYNC: R147.1 R155.1 U4.AJ15(HDA_SYNC)
ACZ_SYNC_AUDIO: R147.2 ; also on sheet 23
AD0: U4.D20(AD0) ; also on sheet 27
AD1: U4.E19(AD1) ; also on sheet 27
AD2: U4.D19(AD2) ; also on sheet 27
AD3: U4.A20(AD3) ; also on sheet 27
AD4: U4.D17(AD4) ; also on sheet 27
AD5: U4.A21(AD5) ; also on sheet 27
AD6: U4.A19(AD6) ; also on sheet 27
AD7: U4.C19(AD7) ; also on sheet 27
AD8: U4.A18(AD8) ; also on sheet 27
AD9: U4.B16(AD9) ; also on sheet 27
AD10: U4.A12(AD10) ; also on sheet 27
AD11: U4.E16(AD11) ; also on sheet 27
AD12: U4.A14(AD12) ; also on sheet 27
AD13: U4.G16(AD13) ; also on sheet 27
AD14: U4.A15(AD14) ; also on sheet 27
AD15: U4.B6(AD15) ; also on sheet 27
AD16: U4.C11(AD16) ; also on sheet 27
AD17: U4.A9(AD17) ; also on sheet 27
AD18: U4.D11(AD18) ; also on sheet 27
AD19: U4.B12(AD19) ; also on sheet 27
AD20: U4.C12(AD20) ; also on sheet 27
AD21: U4.D10(AD21) ; also on sheet 27
AD22: U4.C7(AD22) ; also on sheet 27
AD23: U4.F13(AD23) ; also on sheet 27
AD24: U4.E11(AD24) ; also on sheet 27
AD25: U4.E13(AD25) ; also on sheet 27
AD26: U4.E12(AD26) ; also on sheet 27
AD27: U4.D8(AD27) ; also on sheet 27
AD28: U4.A6(AD28) ; also on sheet 27
AD29: U4.E8(AD29) ; also on sheet 27
AD30: U4.D6(AD30) ; also on sheet 27
AD31: U4.A3(AD31) ; also on sheet 27
BIT_CLK_AUDIO: R158.2 ; also on sheet 23
BOARD_ID0: R217.1 R223.2 U4.AH12(GPIO18)
BOARD_ID1: R222.2 R252.1 U4.AE11(GPIO20)
CBE#0: U4.C17(C/BE0#) ; also on sheet 27
CBE#1: U4.E15(C/BE1#) ; also on sheet 27
CBE#2: U4.F16(C/BE2#) ; also on sheet 27
CBE#3: U4.E17(C/BE3#) ; also on sheet 27
CL_CLK0: U4.F23(CL_CLK0) ; also on sheet 9
CL_DATA0: U4.F22(CL_DATA0) ; also on sheet 9
CL_RST#0: U4.AJ23(CL_RST#) ; also on sheet 9
CL_RST#1: R203.1 U4.AG21(LINKALERT#)
CL_VREF0: C258.1 R211.1 R212.2 U4.D24(CL_VREF0)
CL_VREF1: C259.1 R213.1 R215.2 U4.AH23(CL_VREF1)
CLK_32KX1: C230.2 R133.1 U4.AG25(RTCX1) Y2.1
CLK_32KX2: C232.2 R133.2 U4.AF24(RTCX2) Y2.2
CLK_DMI_ICH: U4.T25(DMI_CLKP) ; also on sheet 4
CLK_DMI_ICH#: U4.T26(DMI_CLKN) ; also on sheet 4
CLK_PWRGD: U4.E1(CK_PWRGD) ; also on sheet 4
CLK_SATA: U4.AC6(SATA_CLKP) ; also on sheet 4
CLK_SATA#: U4.AB7(SATA_CLKN) ; also on sheet 4
CLKRUN#: R178.1 U4.AH11(CLKRUN#/GPIO32)
CLKUSB_48: R220.2 U4.G5(CLK48) ; also on sheet 4
DEVSEL#: RP12.9 U4.D16(DEVSEL#) ; also on sheet 27
DMI_RXN0: U4.V27(DMI0RXN) ; also on sheet 9
DMI_RXN1: U4.Y27(DMI1RXN) ; also on sheet 9
DMI_RXN2: U4.AB26(DMI2RXN) ; also on sheet 9
DMI_RXN3: U4.AD27(DMI3RXN) ; also on sheet 9
DMI_RXP0: U4.V26(DMI0RXP) ; also on sheet 9
DMI_RXP1: U4.Y26(DMI1RXP) ; also on sheet 9
DMI_RXP2: U4.AB25(DMI2RXP) ; also on sheet 9
DMI_RXP3: U4.AD26(DMI3RXP) ; also on sheet 9
DMI_TXN0: U4.U29(DMI0TXN) ; also on sheet 9
DMI_TXN1: U4.W29(DMI1TXN) ; also on sheet 9
DMI_TXN2: U4.AA29(DMI2TXN) ; also on sheet 9
DMI_TXN3: U4.AC29(DMI3TXN) ; also on sheet 9
DMI_TXP0: U4.U28(DMI0TXP) ; also on sheet 9
DMI_TXP1: U4.W28(DMI1TXP) ; also on sheet 9
DMI_TXP2: U4.AA28(DMI2TXP) ; also on sheet 9
DMI_TXP3: U4.AC28(DMI3TXP) ; also on sheet 9
DRI_IRCOMP_R: R159.2 U4.Y23(DMI_ZCOMP) U4.Y24(DMI_IRCOMP)
EXTSMI#_R: R208.1 U4.AE16(GPIO8)
FRAME#: RP12.2 U4.A17(FRAME#) ; also on sheet 27
GATEA20: R135.1 U4.AF13(A20GATE) ; also on sheet 21
GNT0#: R170.1 U4.D7(GNT0#)
GNT1#: U4.C18(GNT1#/GPIO51)
GNT2#: U4.F18(GNT2#/GPIO53) ; also on sheet 27
GPI1: R174.1 U4.AJ8(TACH1/GPIO1)
GPI6: R175.1 U4.AJ9(TACH2/GPIO6)
GPI17: R176.1 U4.AG8(TACH0/GPIO17)
GPI22: R180.1 U4.AG10(SCLOCK/GPIO22)
H_A20M#: U4.AG26(A20M#) ; also on sheet 5
H_DPSLP#: R137.1 U4.AE26(DPSLP#) ; also on sheet 5
H_FERR#: R136.1 U4.AD24(FERR#) ; also on sheet 5
H_IGNNE#: U4.AF27(IGNNE#) ; also on sheet 5
H_INIT#: U4.AE24(INIT#) ; also on sheet 5
H_INTR: U4.AC20(INTR) ; also on sheet 5
H_NMI: U4.AD23(NMI) ; also on sheet 5
H_PWRGD: R140.2 ; also on sheet 5
H_SMI#: R142.2 ; also on sheet 5
H_STPCLK#: U4.AA24(STPCLK#) ; also on sheet 5
H_THERMTRIP_R: R144.1 U4.AE27(THRMTRIP#)
ICH_DPRSTP#: U4.AF26(DPRSTP#) ; also on sheet 31
ICH_INTVRMEN: R148.2 U4.AF25(INTVRMEN)
ICH_LAN_RST#: R204.1 U4.AH20(LAN_RST#)
ICH_RI#: R202.1 U4.AF17(RI#)
INTA#: RP14.7 U4.F9(PIRQA#)
INTB#: RP14.4 U4.B5(PIRQB#)
INTC#: RP14.9 U4.C5(PIRQC#)
INTD#: RP14.8 U4.A10(PIRQD#)
INTE#: RP13.7 U4.F8(PIRQE#/GPIO2) ; also on sheet 27
INTF#: RP14.6 U4.G11(PIRQF#/GPIO3) ; also on sheet 27
INTG#: RP13.3 U4.F12(PIRQG#/GPIO4) ; also on sheet 27
INTH#: RP14.1 U4.B3(PIRQH#/GPIO5) ; also on sheet 27
IRDY#: RP13.1 U4.C8(IRDY#) ; also on sheet 27
IRQ14: U4.Y3(IDEIRQ) ; also on sheet 24
LAD0/FWH0: U4.E5(FWH0/LAD0) ; also on sheet 21 24
LAD1/FWH1: U4.F5(FWH1/LAD1) ; also on sheet 21 24
LAD2/FWH2: U4.G8(FWH2/LAD2) ; also on sheet 21 24
LAD3/FWH3: U4.F6(FWH3/LAD3) ; also on sheet 21 24
LAN2_SWTICH_CTRL: R191.1 U4.AF22(EC_ME_ALERT/GPIO14)
LAN100_SLP: R149.2 U4.AD21(LAN100_SLP)
LDRQ#0: R138.2 R139.2 ; also on sheet 21
LFRAME#/FWH4: U4.C4(FWH4/LFRAME#) ; also on sheet 21 24
LPC_PWRDWN_N: U4.F4(SUS_STAT#/LPCPD#)
MCH_ICH_SYNC: U4.AJ13(MCH_SYNC#) ; also on sheet 9
MPWROK: U4.E3(CLPWROK) ; also on sheet 9 31
PANEL_ID0: R303.1 R476.1 U4.AF9(SLOAD/GPIO38)
PANEL_ID1: R218.1 U4.AJ11(SDATAOUT0/GPIO39)
PANEL_ID2: R219.1 U4.AD10(SDATAOUT1/GPIO48)
PAR: U4.D9(PAR) ; also on sheet 27
PCI_PME#: U4.G7(PME#) ; also on sheet 21
PCIE_RXN0: U4.P27(PERN1) ; also on sheet 19
PCIE_RXN1: U4.M27(PERN2) ; also on sheet 20
PCIE_RXN2: U4.K27(PERN3) ; also on sheet 41
PCIE_RXP0: U4.P26(PERP1) ; also on sheet 19
PCIE_RXP1: U4.M26(PERP2) ; also on sheet 20
PCIE_RXP2: U4.K26(PERP3) ; also on sheet 41
PCIE_TXN0: C245.1 ; also on sheet 19
PCIE_TXN0_C: C245.2 U4.N29(PETN1)
PCIE_TXN1: C247.1 ; also on sheet 20
PCIE_TXN1_C: C247.2 U4.L29(PETN2)
PCIE_TXN2: C618.1 ; also on sheet 41
PCIE_TXN2_C: C618.2 U4.J29(PETN3)
PCIE_TXP0: C246.1 ; also on sheet 19
PCIE_TXP0_C: C246.2 U4.N28(PETP1)
PCIE_TXP1: C248.1 ; also on sheet 20
PCIE_TXP1_C: C248.2 U4.L28(PETP2)
PCIE_TXP2: C619.1 ; also on sheet 41
PCIE_TXP2_C: C619.2 U4.J28(PETP3)
PCIE_WAKE#: R210.1 U4.AE17(WAKE#) ; also on sheet 19 20 41
PCIRST#: U4.G6(PCIRST#) ; also on sheet 27
PCLK_ICH: U4.B10(PCICLK) ; also on sheet 4
PCLK_SMB: R198.1 U4.AJ26(SMBCLK) ; also on sheet 4 28
PDA0: U4.AA4(DA0) ; also on sheet 24
PDA1: U4.AA1(DA1) ; also on sheet 24
PDA2: U4.AB3(DA2) ; also on sheet 24
PDAT_SMB: R199.1 U4.AD19(SMBDATA) ; also on sheet 4 28
PDCS1#: U4.Y6(DCS1#) ; also on sheet 24
PDCS3#: U4.Y5(DCS3#) ; also on sheet 24
PDD0: U4.V1(DD0) ; also on sheet 24
PDD1: U4.U2(DD1) ; also on sheet 24
PDD2: U4.V3(DD2) ; also on sheet 24
PDD3: U4.T1(DD3) ; also on sheet 24
PDD4: U4.V4(DD4) ; also on sheet 24
PDD5: U4.T5(DD5) ; also on sheet 24
PDD6: U4.AB2(DD6) ; also on sheet 24
PDD7: U4.T6(DD7) ; also on sheet 24
PDD8: U4.T3(DD8) ; also on sheet 24
PDD9: U4.R2(DD9) ; also on sheet 24
PDD10: U4.T4(DD10) ; also on sheet 24
PDD11: U4.V6(DD11) ; also on sheet 24
PDD12: U4.V5(DD12) ; also on sheet 24
PDD13: U4.U1(DD13) ; also on sheet 24
PDD14: U4.V2(DD14) ; also on sheet 24
PDD15: U4.U6(DD15) ; also on sheet 24
PDDACK#: U4.Y2(DDACK#) ; also on sheet 24
PDDREQ: U4.W5(DDREQ) ; also on sheet 24
PDIAG: R476.2 ; also on sheet 24
PDIOR#: U4.W4(DIOR#) ; also on sheet 24
PDIOW#: U4.W3(DIOW#) ; also on sheet 24
PERR#: RP13.9 U4.A7(PERR#) ; also on sheet 27
PIORDY: U4.Y1(IORDY) ; also on sheet 24
PLOCK#: RP13.6 U4.B7(PLOCK#) ; also on sheet 27
PLT_RST-R#: U4.AG24(PLTRST#) U6.1(INB) U6.2(INA) U11.1(INB) U11.2(INA) ; also on sheet 9
PLTRST1#: R293.2 U11.4(OUT) ; also on sheet 41
PLTRST#: R172.2 U6.4(OUT) ; also on sheet 19 20 21 24 35
PM_BATLOW#_R: R196.1 U4.AE21(BATLOW#)
PM_BMBUSY#: R187.1 ; also on sheet 9
PM_DPRSLPVR: R200.2 ; also on sheet 9 31
PM_STPCPU#: R197.1 ; also on sheet 4
PM_STPPCI#: R195.1 ; also on sheet 4
PM_THRMTRIP#: R143.1 R144.2 ; also on sheet 5 9
PWRBTN: R192.1 R243.2 ; also on sheet 21 25 30
PWROK: U4.AE23(PWROK) ; also on sheet 9 21 26 31
RCIN#: R134.1 U4.AH14(RCIN#) ; also on sheet 21
REQ0#: RP14.3 U4.A4(REQ0#)
REQ1#: RP12.1 U4.E18(REQ1#/GPIO50)
REQ2#: RP12.3 U4.B19(REQ2#/GPIO52) ; also on sheet 27
REQ3#: RP12.8 U4.A11(REQ3#/GPIO54)
RSMRST#: R207.2 ; also on sheet 19 20 21 34 36 41
RTCRST#: HEAD1.2 U4.AF23(RTCRST#)
RUNTIME_SCI#_R: R184.1 U4.AH9(TACH3/GPIO7)
S4_STATE#: U4.AH27(S4_STATE#/GPIO26) ; also on sheet 32 33
SATA_RX1+: C238.1 U4.AF5(SATA0RXP)
SATA_RX1-: C237.1 U4.AF6(SATA0RXN)
SATA_RX1C+: C238.2 ; also on sheet 29
SATA_RX1C-: C237.2 ; also on sheet 29
SATA_RX2+: C242.1 U4.AF1(SATA2RXP)
SATA_RX2-: C241.1 U4.AF2(SATA2RXN)
SATA_RX2C+: C242.2 ; also on sheet 24
SATA_RX2C-: C241.2 ; also on sheet 24
SATA_RX3+: C252.1 U4.AG4(SATA1RXP)
SATA_RX3-: C251.1 U4.AG3(SATA1RXN)
SATA_RX3C+: C252.2 ; also on sheet 29
SATA_RX3C-: C251.2 ; also on sheet 29
SATA_TX1+: C240.1 U4.AH6(SATA0TXP)
SATA_TX1-: C239.1 U4.AH5(SATA0TXN)
SATA_TX1C+: C240.2 ; also on sheet 29
SATA_TX1C-: C239.2 ; also on sheet 29
SATA_TX2+: C244.1 U4.AE3(SATA2TXP)
SATA_TX2-: C243.1 U4.AE4(SATA2TXN)
SATA_TX2C+: C244.2 ; also on sheet 24
SATA_TX2C-: C243.2 ; also on sheet 24
SATA_TX3+: C254.1 U4.AJ3(SATA1TXP)
SATA_TX3-: C253.1 U4.AJ4(SATA1TXN)
SATA_TX3C+: C254.2 ; also on sheet 29
SATA_TX3C-: C253.2 ; also on sheet 29
SATALED#: R145.1 U4.AF10(SATALED#) ; also on sheet 30
SERIRQ: R182.1 U4.AF12(SERIRQ) ; also on sheet 21
SERR#: RP13.8 U4.F10(SERR#) ; also on sheet 27
SIOBTN: R243.1 U4.C2(PWRBTN#) ; also on sheet 21 36
SLP_S3#: R186.1 ; also on sheet 21 32 33 34
SLP_S4#: T29.1 U4.AF21(SLP_S4#)
SLP_S5#: R270.1 ; also on sheet 21
SM_CLK_ME: R205.1 U4.AC17(SMLINK0)
SM_DATA_ME: R206.1 U4.AE19(SMLINK1)
SM_INTRUDER#: R132.1 U4.AD22(INTRUDER#)
SMB_ALERT#: R188.1 R209.1 ; also on sheet 28
SPI_ARB: R194.1 U4.E22(SPI_CS1#)
SPI_CE#: R161.1 U3.1(CE#)
SPI_SCLK: R160.1 U3.6(SCK)
SPI_SI: R163.1 U3.5(SI)
SPI_SO: R164.2 U4.F21(SPI_MISO)
STOP#: RP12.4 U4.C16(STOP#) ; also on sheet 27
SYS_RST#: R320.1 U4.AD15(SYS_RESET#) ; also on sheet 5 25 26
THERM_ALERT#: R201.2 U4.AC13(THRM#)
TRDY#: RP12.6 U4.C9(TRDY#) ; also on sheet 27
USB_RBIAS_PN: R169.1 U4.F2(USBRBIAS#) U4.F3(USBRBIAS)
USBOC#0: RP15.8 U4.AJ19(OC0#)
USBOC#1: RP15.7 U4.AG16(OC1#/GPIO40)
USBOC#2: RP15.1 U4.AG15(OC2#/GPIO41)
USBOC#3: RP15.6 U4.AE15(OC3#/GPIO42)
USBOC#4: RP15.3 U4.AF15(OC4#/GPIO43)
USBOC#5: RP15.9 U4.AG17(OC5#/GPIO29)
USBOC#6: RP15.4 U4.AD12(OC6#/GPIO30)
USBOC#7: RP15.2 U4.AJ18(OC7#/GPIO31)
USBOC#8: R166.1 U4.AD14(OC8#)
USBOC#9: R167.1 U4.AH18(OC9#)
USBP0N: U4.G3(USBP0N) ; also on sheet 29
USBP0P: U4.G2(USBP0P) ; also on sheet 29
USBP1N: U4.H5(USBP1N) ; also on sheet 29
USBP1P: U4.H4(USBP1P) ; also on sheet 29
USBP2N: U4.H2(USBP2N) ; also on sheet 29
USBP2P: U4.H1(USBP2P) ; also on sheet 29
USBP3N: U4.J3(USBP3N) ; also on sheet 29
USBP3P: U4.J2(USBP3P) ; also on sheet 29
USBP4N: U4.K5(USBP4N) ; also on sheet 40
USBP4P: U4.K4(USBP4P) ; also on sheet 40
USBP5N: U4.K2(USBP5N) ; also on sheet 40
USBP5P: U4.K1(USBP5P) ; also on sheet 40
VR_PWRGD: U4.AJ20(VRMPWRGD) ; also on sheet 31
WATCHDOG_GPO: R305.2 ; also on sheet 26
WATCHDOG_GPO_R: R189.1 R305.1 U4.AJ24(ME_EC_ALERT/GPIO10)
N3388001: R160.2 U4.C23(SPI_CLK)
N3388003: R161.2 U4.B23(SPI_CS0#)
N3388007: R163.2 U4.D23(SPI_MOSI)
N7188613: C274.1 C275.2 L7.1 U4.R29(VCCDMIPLL)
N7395005: T41.1 U4.G22(VCCCL1_05)
N7398481: C299.2 R229.2 U4.A24(VCCGLANPLL)
N23496698: L7.2 R228.1
N49909755: C301.1 U4.A22(VCCCL1_5)
N52519290: R162.2 U3.7(HOLD#)
N55017868: R164.1 U3.2(SO)
N55017890: R165.1 U3.3(WP#)
N69377500: R177.1 U4.AJ12(SATA0GP/GPIO21)
N69377534: R185.2 T28.1
N69377536: R179.1 U4.AJ10(SATA1GP/GPIO19)
N69377538: R186.2 U4.AG23(SLP_S3#)
N69377628: R200.1 U4.AJ14(DPRSLPVR/GPIO16)
N69377651: R181.1 U4.AF11(SATA2GP/GPIO36)
N69377655: R183.1 U4.AG11(SATA3GP/GPIO37)
N69377673: R207.1 U4.AG27(RSMRST#)
N69377724: R187.2 U4.AG12(BMBUSY#/GPIO0)
N69377729: R188.2 U4.AG22(SMBALERT#/GPIO11)
N69377903: T31.1 U4.AJ22(TP7)
N69377944: C260.1 R220.1
N69377946: C261.1 R221.1
N69465251: R197.2 U4.AG18(STP_CPU#/GPIO25)
N69472458: R195.2 U4.AE20(STP_PCI#/GPIO15)
N69629581: R185.1 U4.D3(SUSCLK)
N79910082: T27.1 U4.AA23(TP8)
N79910167: R141.2 U4.C25(GLAN_COMPO) U4.D25(GLAN_COMPI)
N79910414: C231.2 HEAD1.3 R130.1
N79910741: R146.2 U4.AG1(SATARBIAS#) U4.AG2(SATARBIAS)
N79910912: R139.1 U4.E6(LDRQ1#/GPIO23)
N79911006: R142.1 U4.AG28(SMI#)
N79911011: R138.1 U4.G9(LDRQ0#)
N79911037: R140.1 U4.AG29(CPUPWRGD/GPIO49)
N79911262: BAT1.1(+) R131.1
N108702963: R287.2 U4.AD9(SPKR)
N111014685: R270.2 U4.AD18(SLP_S5#)
N120021341: T36.1 U4.AF20(VCCSUS1_05[2])
N120021343: T35.1 U4.J6(VCCSUS1_05[1])
N120021345: T40.1 U4.G18(VCCLAN1_05[2])
N120021346: T39.1 U4.F17(VCCLAN1_05[1])
N120021347: T38.1 U4.J7(VCCSUS1_5[2])
N120021348: T37.1 U4.AC16(VCCSUS1_5[1])
N126180538: T34.1 U4.AJ21(TP3)
N126180539: R214.2 U4.AG19(WOL_EN/GPIO9)
N126180540: T32.1 U4.AE18(CL_CLK1)
N126180541: T33.1 U4.AF19(CL_DATA1)

Not connected (* = marked no-connect by the designer): D5 2*; D6 2*; RP12 7*; RP13 2* 4*; RP14 2*; U4 AC19(GPIO12)* AD13(HDA_SDIN3)* AD16(QRT_STATE1/GPIO28)* AE10(HDA_DOCK_EN#/GPIO33)* AG13(SATACLKREQ#/GPIO35)* AG14(HDA_DOCK_RST#/GPIO34)* AH15(HDA_SDIN2)* AH17(HDA_SDIN1)* AH21(GLAN_DOCK#/GPIO13)* AH25(QRT_STATE0/GPIO27)* AJ25(SLP_M#)* AJ27(MEM_LED/GPIO24)* B21(LAN_RXD1)* B24(GLAN_CLK)* C10(GNT3#/GPIO55)* C20(LAN_TXD2)* C21(LAN_RXD0)* C22(LAN_RXD2)* C28(PETP6/GLAN_TXP)* C29(PETN6/GLAN_TXN)* D21(LAN_TXD0)* D22(LAN_RSTSYNC)* D26(PERP6/GLAN_RXP)* D27(PERN6/GLAN_RXN)* E20(LAN_TXD1)* E28(PETP5)* E29(PETN5)* F26(PERP5)* F27(PERN5)* G28(PETP4)* G29(PETN4)* H26(PERP4)* H27(PERN4)* L2(USBP6P)* L3(USBP6N)* M1(USBP8P)* M2(USBP8N)* M4(USBP7P)* M5(USBP7N)* N2(USBP9P)* N3(USBP9N)*

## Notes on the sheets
sheet 15
- CKL:C1/C2: 18pF -> CL:12.5pF
  C1/C: 10pF -> CL Value =
  8.5pF
- Internal PU
- Should be 2" close ICH8
- Should be place
  <0.1" close ICH8
- 25mils/15mils
- Place within 500
  mils of ICH8
- ICH8 internal VR
  enable strap
- INTVRMEN
  VCCSUS1_05,VccSus1_5,
  VccCL1_5
- LAN100_SLP
  VccLAN1_05,VccCL1_05
- PCIE
  CFG
- ACZ_SDOUT BIT1
- ACZ_SYNC BIT0
- Enable
- 1
- 1
- 1 PCIE *4
- 1
- 1
- Disable
- 0
- 0
- 4 PCIE *1
- 0
- 0
sheet 16
- 15/15mils
- Place within 500
  mils of ICH8
- CKL use 10Kohm
- 25mils/15mils
- Place within 500
  mils of ICH8
- ICH8 Boot BIOS select
- STRAP
- GNT#0
   R1
- SPI_CS1#
   R2
- LPC
- 11
- UNSTUFF
- UNSTUFF
- PCI
- 10
- UNSTUFF
- STUFF
- *SPI
- 01
- STUFF
- UNSTUFF
sheet 17
- GPIO25 /Suspend rail is a HW strap , don't pull down .
- PANEL ID:
- Board ID
- ID1
- ID0
- PANEL_ID2
- PANEL_ID1
- PANEL_ID0
- 00
- ID3
- XGA
- 0
- 1
- PATA, PCMCIA
- ID4
- UXGA
- 1
- 0
- 01
- 0
- 1
- ID5
- SXGA+
- 1
- 0
- PATA, NEW
- ID6
- SXGA
- 1
- 1
- 10
- SATA, PCMCIA
- ID7
- NC
- 1
- 1
- 11
- PATA, NEW
- 1
sheet 18
- 940mA
- 6mA
- 10mA
- 50mA
- 770mA
- 14mA
- 270mA
- 50mA
- 56mA
- 640mA
- 10mA
- 45mA
- 10mA
- 40mA
- Controler Link power supply.
  when internal VRM is enabled,
  they can left NC
- nicole update 7/27
- 1.Level 1 Environment-related Substances Should NEVER be Used.
  2.Purchase ink, paint, wire rods and molding resins only from the business partners that Sony approves as Green Partners.
